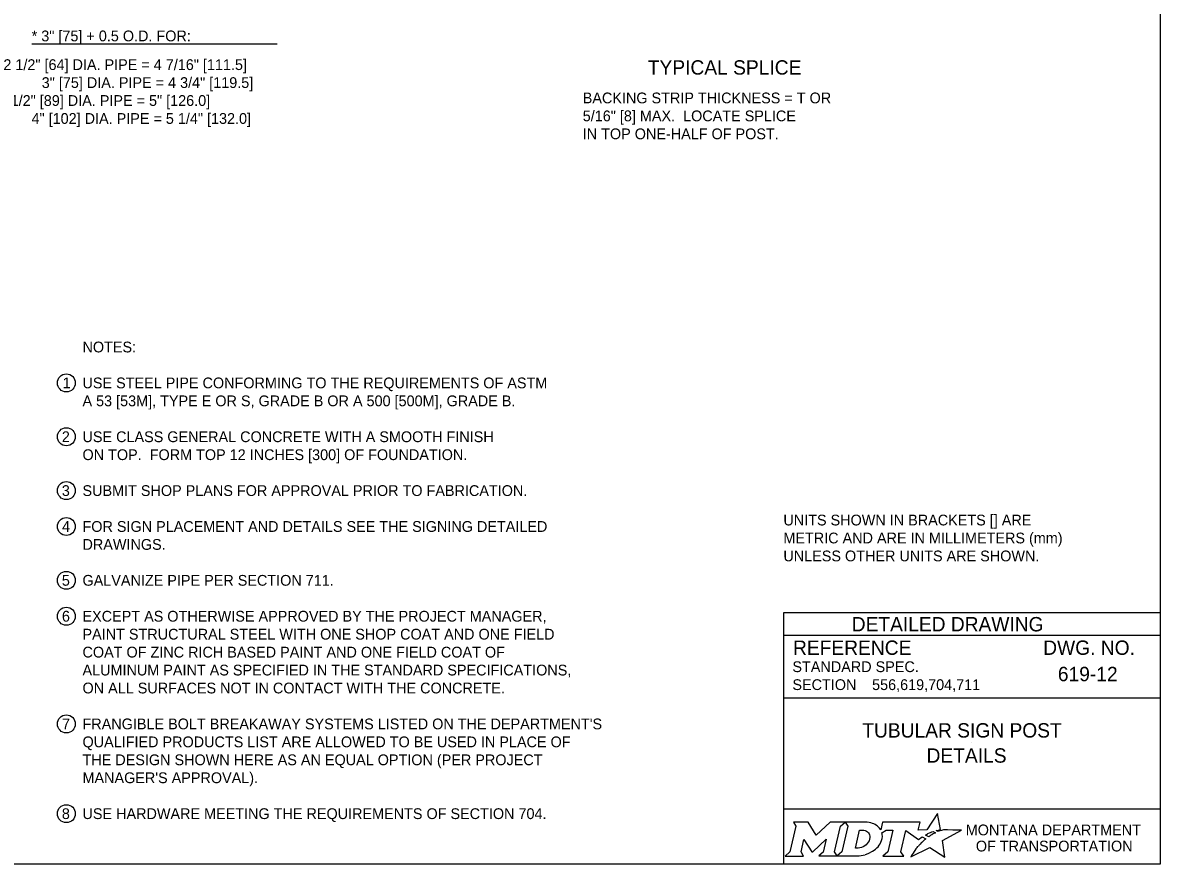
# Model space of a CAD drawing. Extents: x 49991 to 81321, y 49988 to 50028.
# Drawn here: x 50010.41 to 50016.75, y 49987.8 to 49992.49 of the extents above; entities that cross this region are included whole.
import ezdxf

# ---------------------------------------------------------------- set-up
doc = ezdxf.new("R2010")
doc.units = 0
for name, color, linetype in [('Default', 7, 'Continuous'), ('Level 1', 7, 'Continuous'), ('Level 2', 7, 'Continuous'), ('Level 3', 7, 'Continuous'), ('Level 5', 7, 'Continuous')]:
    doc.layers.add(name, color=color, linetype=linetype)

msp = doc.modelspace()

# ---------------------------------------------------------------- linework, layer by layer
at = {"layer": 'Default'}
for points in [[(50014.7056, 49988.0338), (50014.7197, 49988.0104), (50014.6862, 49987.8671), (50014.6605, 49987.8446), (50014.7621, 49987.8446), (50014.7486, 49987.8674), (50014.7648, 49987.9375), (50014.8085, 49987.8685), (50014.8138, 49987.8685), (50014.8889, 49987.938), (50014.8725, 49987.8669), (50014.8478, 49987.8449), (50014.9494, 49987.8449), (50014.9356, 49987.8682), (50014.9688, 49988.0106)], [(50014.9688, 49988.0106), (50014.9941, 49988.0338), (50014.9117, 49988.0338), (50014.8321, 49987.9608), (50014.7876, 49988.0335), (50014.7056, 49988.0338)], [(50015.1077, 49988.0338), (50014.9941, 49988.0338), (50015.0088, 49988.0109), (50014.9749, 49987.8671), (50014.9494, 49987.8449), (50015.06, 49987.8449)], [(50015.5126, 49987.9811), (50015.5023, 49987.9867), (50015.5139, 49987.9895), (50015.5255, 49987.9915), (50015.5081, 49988.0816), (50015.4486, 49987.9903), (50015.4013, 49987.9896), (50015.4116, 49988.0337), (50015.2024, 49988.0338), (50015.1923, 49987.9913), (50015.1865, 49987.9996)], [(50015.1317, 49987.9471), (50015.1305, 49987.939), (50015.1273, 49987.9297), (50015.1231, 49987.9215), (50015.1175, 49987.914), (50015.111, 49987.9071), (50015.1031, 49987.9008), (50015.0948, 49987.8961), (50015.0857, 49987.8922), (50015.0766, 49987.8899), (50015.0674, 49987.889), (50015.0515, 49987.889), (50015.0751, 49987.989), (50015.0911, 49987.989), (50015.0987, 49987.9884), (50015.1063, 49987.9865), (50015.1129, 49987.9835), (50015.119, 49987.9793), (50015.1238, 49987.9743), (50015.1275, 49987.9683), (50015.1302, 49987.9621), (50015.1318, 49987.9547), (50015.1318, 49987.9517), (50015.1317, 49987.9471)], [(50015.1991, 49987.9747), (50015.2237, 49987.9878), (50015.2606, 49987.9878), (50015.232, 49987.8673), (50015.2045, 49987.8446), (50015.3207, 49987.8446), (50015.3037, 49987.8675), (50015.3319, 49987.9877), (50015.4032, 49987.936), (50015.4243, 49987.9511), (50015.444, 49987.9402)], [(50015.3882, 49987.8843), (50015.3729, 49987.8599), (50015.3682, 49987.8524), (50015.3624, 49987.8438), (50015.3601, 49987.8395), (50015.4654, 49987.8926), (50015.5493, 49987.8375), (50015.5362, 49987.9302), (50015.6431, 49987.9886), (50015.5938, 49987.9894), (50015.5637, 49987.9898), (50015.5429, 49987.9901), (50015.5361, 49987.9886), (50015.5312, 49987.9874), (50015.5228, 49987.9851), (50015.5126, 49987.9811)], [(50015.4622, 49987.9535), (50015.4598, 49987.9518), (50015.4415, 49987.9614), (50015.4518, 49987.9671), (50015.4559, 49987.9693), (50015.4645, 49987.9733), (50015.4702, 49987.9759), (50015.4781, 49987.9789), (50015.4854, 49987.9816), (50015.4972, 49987.9742), (50015.4932, 49987.9721), (50015.4886, 49987.9696), (50015.4844, 49987.9674), (50015.4794, 49987.9645), (50015.4775, 49987.9634), (50015.4748, 49987.9618), (50015.4723, 49987.9604), (50015.47, 49987.9588), (50015.4674, 49987.957), (50015.4647, 49987.9552), (50015.4622, 49987.9535)], [(50015.4021, 49987.9004), (50015.4021, 49987.9004)], [(50015.1057, 49987.8522), (50015.1141, 49987.8548), (50015.1271, 49987.8602), (50015.1475, 49987.8712)]]:
    msp.add_lwpolyline(points, dxfattribs=at)
for centre, radius, start, end in [((50015.1308, 49987.9554), 0.0709, 339.53292, 15.85821), ((50015.0868, 49987.9727), 0.1183, 300.91025, 339.13831)]:
    msp.add_arc(centre, radius, start, end, dxfattribs=at)
for centre, major_axis, ratio, start_param, end_param in [((50015.1056, 49987.9864), (0.0834, -0.0037), 0.568097, 0.61298, 1.570796), ((50015.1612, 49987.9937), (0.0361, -0.0295), 0.469099, 1.225588, 1.570796), ((50015.3952, 49987.8923), (-0.00694, -0.00806), 0.008222, 0, 3.137361), ((50015.4119, 49987.9106), (-0.0098, -0.0102), 0.016458, 3.141593, 6.279097), ((50015.4329, 49987.9305), (-0.0112, -0.0097), 0.021651, 3.157348, 6.283185), ((50015.0603, 49987.9932), (0, 0.1484), 0.987302, 3.139398, 3.456847)]:
    msp.add_ellipse(centre, major_axis=major_axis, ratio=ratio, start_param=start_param, end_param=end_param, dxfattribs=at)
at = {"layer": 'Level 1'}
msp.add_lwpolyline([(49999.3835, 49998.9992), (50016.7501, 49998.9992), (50016.7501, 49987.7988), (49999.3835, 49987.7988)], close=True, dxfattribs=at)
at = {"layer": 'Level 2'}
msp.add_line((50011.8302, 49992.3678), (50010.4614, 49992.3678), dxfattribs=at)
for centre in [(50010.6546, 49990.4806), (50010.6546, 49990.1806), (50010.6546, 49989.8806), (50010.6546, 49989.6806), (50010.6546, 49989.3806), (50010.6546, 49989.1806), (50010.6546, 49988.5806), (50010.6546, 49988.0806)]:
    msp.add_circle(centre, 0.05, dxfattribs=at)
at = {"layer": 'Level 3'}
msp.add_line((50015.924, 49989.1426), (50015.924, 49989.1426), dxfattribs=at)
at = {"layer": 'Level 5'}
for p, q in [((50016.7501, 49989.1988), (50014.6501, 49989.1988)), ((50014.6501, 49989.1988), (50014.6501, 49987.7988)), ((50016.7501, 49989.0738), (50014.6501, 49989.0738)), ((50016.3862, 49988.8587), (50016.3862, 49988.8587)), ((50015.1444, 49988.7993), (50015.1444, 49988.7993)), ((50016.7501, 49988.7238), (50014.6501, 49988.7238)), ((50015.7001, 49988.4747), (50015.7001, 49988.4747)), ((50016.7501, 49988.1057), (50014.6501, 49988.1057))]:
    msp.add_line(p, q, dxfattribs=at)

# ---------------------------------------------------------------- texts
at = {"layer": 'Default'}
for s, p in [('MONTANA DEPARTMENT', (50015.6663, 49987.96)), ('OF TRANSPORTATION', (50015.7225, 49987.87))]:
    msp.add_text(s, height=0.06, dxfattribs=at).set_placement(p)
at = {"layer": 'Level 2'}
for s, height, p in [('* 3" [75] + 0.5 O.D. FOR:', 0.06, (50010.4614, 49992.3838)), ('2 1/2" [64] DIA. PIPE = 4 7/16" [111.5]', 0.06, (50010.3038, 49992.2238)), ('TYPICAL SPLICE', 0.08, (50013.8944, 49992.1983)), ('3" [75] DIA. PIPE = 4 3/4" [119.5]', 0.06, (50010.5174, 49992.1238)), ('3 1/2" [89] DIA. PIPE = 5" [126.0]', 0.06, (50010.2774, 49992.0238)), ('BACKING STRIP THICKNESS = T OR', 0.06, (50013.5321, 49992.0383)), ('4" [102] DIA. PIPE = 5 1/4" [132.0]', 0.06, (50010.4605, 49991.9238)), ('5/16" [8] MAX.  LOCATE SPLICE', 0.06, (50013.5321, 49991.9383)), ('IN TOP ONE-HALF OF POST.', 0.06, (50013.5321, 49991.8383)), ('NOTES:', 0.06, (50010.7446, 49990.6506)), ('1', 0.06, (50010.6339, 49990.4506)), ('USE STEEL PIPE CONFORMING TO THE REQUIREMENTS OF ASTM', 0.06, (50010.7446, 49990.4506)), ('A 53 [53M], TYPE E OR S, GRADE B OR A 500 [500M], GRADE B.', 0.06, (50010.7446, 49990.3506)), ('2', 0.06, (50010.6294, 49990.1506)), ('USE CLASS GENERAL CONCRETE WITH A SMOOTH FINISH', 0.06, (50010.7446, 49990.1506)), ('ON TOP.  FORM TOP 12 INCHES [300] OF FOUNDATION.', 0.06, (50010.7446, 49990.0506)), ('3', 0.06, (50010.6294, 49989.8506)), ('SUBMIT SHOP PLANS FOR APPROVAL PRIOR TO FABRICATION.', 0.06, (50010.7446, 49989.8506)), ('UNITS SHOWN IN BRACKETS [] ARE ', 0.06, (50014.6501, 49989.6865)), ('4', 0.06, (50010.6306, 49989.6506)), ('FOR SIGN PLACEMENT AND DETAILS SEE THE SIGNING DETAILED', 0.06, (50010.7446, 49989.6506)), ('DRAWINGS.', 0.06, (50010.7446, 49989.5506)), ('METRIC AND ARE IN MILLIMETERS (mm) ', 0.06, (50014.6501, 49989.5865)), ('UNLESS OTHER UNITS ARE SHOWN.', 0.06, (50014.6501, 49989.4865)), ('5', 0.06, (50010.6296, 49989.3506)), ('GALVANIZE PIPE PER SECTION 711.', 0.06, (50010.7446, 49989.3506)), ('6', 0.06, (50010.63, 49989.1506)), ('EXCEPT AS OTHERWISE APPROVED BY THE PROJECT MANAGER, ', 0.06, (50010.7446, 49989.1506)), ('PAINT STRUCTURAL STEEL WITH ONE SHOP COAT AND ONE FIELD ', 0.06, (50010.7446, 49989.0506)), ('COAT OF ZINC RICH BASED PAINT AND ONE FIELD COAT OF ', 0.06, (50010.7446, 49988.9506)), ('ALUMINUM PAINT AS SPECIFIED IN THE STANDARD SPECIFICATIONS, ', 0.06, (50010.7446, 49988.8506)), ('619-12', 0.08, (50016.1796, 49988.8187)), ('ON ALL SURFACES NOT IN CONTACT WITH THE CONCRETE.', 0.06, (50010.7446, 49988.7506)), ('556,619,704,711', 0.06, (50015.1444, 49988.7693)), ('7', 0.06, (50010.6308, 49988.5506)), ("FRANGIBLE BOLT BREAKAWAY SYSTEMS LISTED ON THE DEPARTMENT'S ", 0.06, (50010.7446, 49988.5506)), ('TUBULAR SIGN POST', 0.08, (50015.0896, 49988.5047)), ('QUALIFIED PRODUCTS LIST ARE ALLOWED TO BE USED IN PLACE OF ', 0.06, (50010.7446, 49988.4506)), ('THE DESIGN SHOWN HERE AS AN EQUAL OPTION (PER PROJECT ', 0.06, (50010.7446, 49988.3506)), ('DETAILS', 0.08, (50015.4478, 49988.3647)), ("MANAGER'S APPROVAL).", 0.06, (50010.7446, 49988.2506)), ('8', 0.06, (50010.6296, 49988.0506)), ('USE HARDWARE MEETING THE REQUIREMENTS OF SECTION 704.', 0.06, (50010.7446, 49988.0506))]:
    msp.add_text(s, height=height, dxfattribs=at).set_placement(p)
at = {"layer": 'Level 5'}
for s, height, p in [('DETAILED DRAWING', 0.0799, (50015.0311, 49989.0963)), ('REFERENCE', 0.08, (50014.7037, 49988.9654)), ('DWG. NO.', 0.08, (50016.0979, 49988.9654)), ('STANDARD SPEC.', 0.06, (50014.7004, 49988.8694)), ('SECTION', 0.06, (50014.7004, 49988.7694))]:
    msp.add_text(s, height=height, dxfattribs=at).set_placement(p)

doc.saveas('drawing.dxf')
